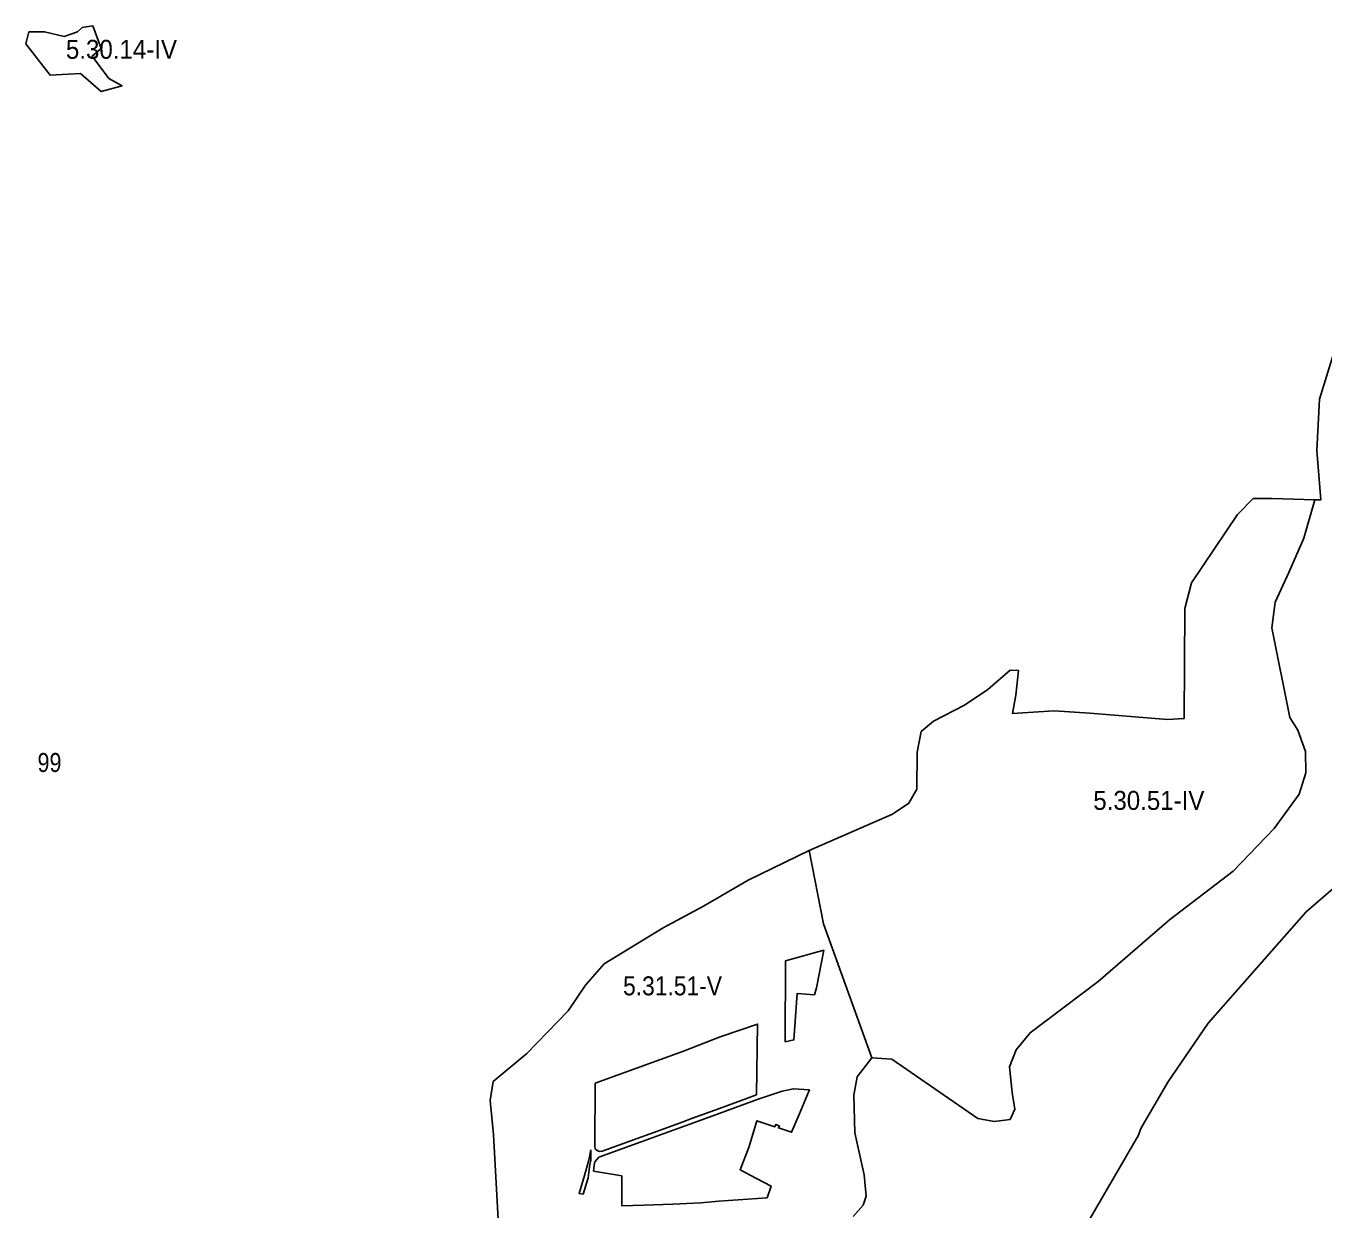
# Model space of a CAD drawing. Extents: x -589769 to -586623, y -1119592 to -1116833.
# Drawn here: x -589492 to -588124, y -1118080 to -1116833 of the extents above; entities that cross this region are included whole.
import ezdxf

# ---------------------------------------------------------------- set-up
doc = ezdxf.new("R2010")
doc.units = 0
doc.header["$LTSCALE"] = 8
doc.layers.add('40', color=7, linetype='Continuous', lineweight=25)
doc.layers.add('8', color=7, linetype='Continuous', lineweight=25)
doc.layers.add('41', color=7, linetype='Continuous')

msp = doc.modelspace()

# ---------------------------------------------------------------- linework, layer by layer
at = {"layer": '40'}
for points in [[(-589489.5, -1116839), (-589473, -1116839), (-589452, -1116844), (-589438, -1116839), (-589433, -1116834.5), (-589422.043, -1116832.733), (-589413, -1116856.5), (-589422.5, -1116864.5), (-589405, -1116888), (-589391, -1116896), (-589413, -1116902), (-589435, -1116883), (-589467, -1116884.5), (-589492.5, -1116851.5)], [(-588132.5, -1117332.5), (-588144, -1117373), (-588160, -1117409), (-588174.5, -1117440.5), (-588178, -1117467.5), (-588159, -1117562), (-588150.5, -1117575.5), (-588142.5, -1117598), (-588142, -1117620.5), (-588149, -1117643), (-588175.5, -1117679), (-588218.5, -1117724), (-588286, -1117775.5), (-588361, -1117840.5), (-588433, -1117894.5), (-588447.5, -1117912.5), (-588454.5, -1117930.5), (-588452, -1117957.5), (-588449, -1117975), (-588454, -1117986), (-588471, -1117988), (-588488, -1117985), (-588579, -1117922.5), (-588600, -1117921), (-588651, -1117779.5), (-588666, -1117702.5), (-588578, -1117664), (-588561, -1117652.5), (-588552.5, -1117637.5), (-588552, -1117598.5), (-588548, -1117577), (-588535, -1117566), (-588502, -1117549), (-588477.5, -1117532.5), (-588454, -1117512), (-588445, -1117512.5), (-588448, -1117538.5), (-588451.5, -1117558), (-588407.5, -1117555), (-588370, -1117557.5), (-588288, -1117564), (-588270.5, -1117563), (-588269.5, -1117447), (-588262.5, -1117420), (-588214, -1117348), (-588197.5, -1117331), (-588177.5, -1117331)]]:
    msp.add_lwpolyline(points, close=True, dxfattribs=at)
for points in [[(-588102.5, -1117145.5), (-588127.5, -1117226.5), (-588130.5, -1117280.5), (-588126, -1117332.5), (-588132.5, -1117332.5), (-588177.5, -1117331), (-588197.5, -1117331), (-588214, -1117348), (-588262.5, -1117420), (-588269.5, -1117447), (-588270.5, -1117563), (-588288, -1117564), (-588370, -1117557.5), (-588407.5, -1117555), (-588451.5, -1117558), (-588448, -1117538.5), (-588445, -1117512.5), (-588454, -1117512), (-588477.5, -1117532.5), (-588502, -1117549), (-588535, -1117566), (-588548, -1117577), (-588552, -1117598.5), (-588552.5, -1117637.5), (-588561, -1117652.5), (-588578, -1117664), (-588666, -1117702.5), (-588730.5, -1117733.5), (-588777.5, -1117761), (-588820, -1117784), (-588882.5, -1117822), (-588902, -1117844.5), (-588920.5, -1117871.5), (-588964, -1117916.5), (-588999.5, -1117946), (-589002.5, -1117966), (-588999, -1118002), (-588994, -1118098)], [(-588619.5, -1118088.5), (-588609, -1118076.5), (-588606, -1118067), (-588608, -1118044.5), (-588618, -1118000), (-588619, -1117960.5), (-588615.5, -1117941), (-588600, -1117921), (-588579, -1117922.5), (-588488, -1117985), (-588471, -1117988), (-588454, -1117986), (-588449, -1117975), (-588452, -1117957.5), (-588454.5, -1117930.5), (-588447.5, -1117912.5), (-588433, -1117894.5), (-588361, -1117840.5), (-588286, -1117775.5), (-588218.5, -1117724), (-588175.5, -1117679), (-588149, -1117643), (-588142, -1117620.5), (-588142.5, -1117598), (-588150.5, -1117575.5), (-588159, -1117562), (-588178, -1117467.5), (-588174.5, -1117440.5), (-588160, -1117409), (-588144, -1117373), (-588132.5, -1117332.5), (-588126, -1117332.5), (-588130.5, -1117280.5), (-588127.5, -1117226.5), (-588102.5, -1117145.5)], [(-588994, -1118098), (-588999, -1118002), (-589002.5, -1117966), (-588999.5, -1117946), (-588964, -1117916.5), (-588920.5, -1117871.5), (-588902, -1117844.5), (-588882.5, -1117822), (-588820, -1117784), (-588777.5, -1117761), (-588730.5, -1117733.5), (-588666, -1117702.5), (-588651, -1117779.5), (-588600, -1117921), (-588615.5, -1117941), (-588619, -1117960.5), (-588618, -1118000), (-588608, -1118044.5), (-588606, -1118067), (-588609, -1118076.5), (-588619.5, -1118088.5)], [(-588114.5, -1118516), (-588165.5, -1118527.5), (-588213.5, -1118543), (-588210.5, -1118527), (-588208, -1118492), (-588214.5, -1118456), (-588228.5, -1118425.5), (-588261, -1118384), (-588339, -1118321), (-588359.5, -1118298.5), (-588388, -1118238), (-588402, -1118186.5), (-588403, -1118166), (-588371.5, -1118094), (-588318.5, -1118002.5), (-588316, -1117995.5), (-588287.5, -1117946.5), (-588245, -1117884.5), (-588141.5, -1117767), (-588085, -1117718)], [(-588085, -1117718), (-588141.5, -1117767), (-588245, -1117884.5), (-588287.5, -1117946.5), (-588316, -1117995.5), (-588318.5, -1118002.5), (-588371.5, -1118094)]]:
    msp.add_lwpolyline(points, dxfattribs=at)
at = {"layer": '8'}
for points in [[(-588650.575, -1117807.3), (-588690.929, -1117818.704), (-588691.27, -1117904.09), (-588682.18, -1117902.06), (-588678.86, -1117853.3), (-588660.45, -1117854.43), (-588658.26, -1117847.01)], [(-588891.961, -1117947.745), (-588798.739, -1117913.83), (-588760.04, -1117898.887), (-588720.48, -1117885.36), (-588721.77, -1117959.96), (-588760.63, -1117974.34), (-588789.02, -1117984.7), (-588800.03, -1117988.72), (-588826, -1117998.2), (-588884.59, -1118019.59), (-588887.31, -1118019.89), (-588889.89, -1118018.89), (-588891.71, -1118016.81), (-588892.36, -1118014.14)], [(-588888.04, -1118025.8), (-588892.19, -1118030.82), (-588892.95, -1118034.36), (-588893.46, -1118040.37), (-588863.81, -1118045.57), (-588863.82, -1118055.06), (-588863.84, -1118076.94), (-588840.63, -1118076.51), (-588809.79, -1118075.39), (-588780.43, -1118074), (-588761.3, -1118072.29), (-588710.52, -1118068.5), (-588706.27, -1118056.2), (-588721.58, -1118048.14), (-588738.93, -1118039.02), (-588729.5, -1118014.51), (-588721.38, -1117987.35), (-588702.27, -1117993.69), (-588701.09, -1117991.21), (-588697.59, -1117992.86), (-588698.58, -1117994.92), (-588684.62, -1117999.55), (-588676.56, -1117980.86), (-588669.62, -1117964.03), (-588665.8, -1117954.76), (-588682.64, -1117953.66), (-588694.42, -1117956.25), (-588719.92, -1117964.64), (-588760.88, -1117979.71), (-588779.21, -1117986.35), (-588808.44, -1117996.95), (-588843.2, -1118009.54), (-588863.78, -1118017)], [(-588896.549, -1118017.909), (-588898.585, -1118029), (-588903.101, -1118045.133), (-588908.818, -1118064.029), (-588904.62, -1118064.73), (-588899.14, -1118047.42), (-588897.36, -1118033.39), (-588896.56, -1118029.25)]]:
    msp.add_lwpolyline(points, close=True, dxfattribs=at)

# ---------------------------------------------------------------- texts
at = {"layer": '41'}
for s, width, p in [('5.30.14-IV', 0.95, (-589450.313, -1116867.375)), ('99', 0.85, (-589480.281, -1117619.5)), ('5.30.51-IV', 0.95, (-588366.25, -1117659.5)), ('5.31.51-V', 0.9, (-588862.431, -1117855.085))]:
    msp.add_text(s, height=20, dxfattribs=dict(at, width=width)).set_placement(p)

doc.saveas('drawing.dxf')
